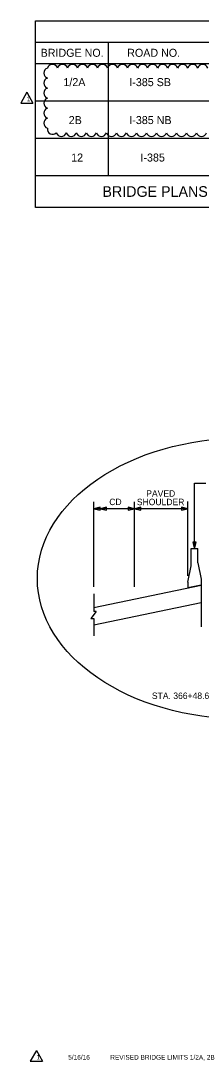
# Model space of a CAD drawing. Extents: x 4832 to 5477, y 4935 to 5220.
# Drawn here: x 5015.4 to 5049.2, y 5022.4 to 5217.4 of the extents above; entities that cross this region are included whole.
import ezdxf

# ---------------------------------------------------------------- set-up
doc = ezdxf.new("R2010")
doc.units = 0
for name, color, linetype in [('Level 2', 7, 'Continuous'), ('Level 3', 7, 'Continuous'), ('Level 42', 7, 'Continuous'), ('RD_SHT_TX', 7, 'Continuous'), ('RD_SHT_Typical', 7, 'Continuous'), ('RD_TX_TitleSht', 7, 'Continuous'), ('RD_TX_TypSect', 7, 'Continuous'), ('RD_XS_PaveShd', 7, 'Continuous'), ('TERMINATOR', 7, 'Continuous')]:
    doc.layers.add(name, color=color, linetype=linetype)

# ---------------------------------------------------------------- blocks, each defined once
blk = doc.blocks.new('AH')
at = {"layer": 'TERMINATOR'}
blk.add_lwpolyline([(-6, 1.5), (0, 0), (-6, -1.5)], close=True, dxfattribs=at)

msp = doc.modelspace()

# ---------------------------------------------------------------- linework, layer by layer
at = {"layer": 'Level 2'}
for p, q in [((5047.34, 5115.27), (5047.35, 5118.48)), ((5047.35, 5118.48), (5048.59, 5118.48)), ((5048.6, 5115.8), (5048.59, 5118.48)), ((5046.72, 5112.21), (5047.34, 5115.27)), ((5048.6, 5115.8), (5049.22, 5112.73)), ((5046.72, 5112.21), (5046.72, 5111.11)), ((5049.22, 5111.63), (5046.72, 5111.11)), ((5049.22, 5112.73), (5049.22, 5111.63))]:
    msp.add_line(p, q, dxfattribs=at)
at = {"layer": 'Level 3'}
for p, q in [((5018.15, 5188.42), (5018.15, 5217.42)), ((5018.15, 5217.42), (5115.75, 5217.42)), ((5018.15, 5213.42), (5115.75, 5213.42)), ((5018.15, 5209.42), (5115.75, 5209.42)), ((5018.15, 5202.42), (5115.75, 5202.42)), ((5018.15, 5195.42), (5115.75, 5195.42)), ((5018.15, 5188.42), (5115.75, 5188.42)), ((5031.75, 5188.42), (5115.75, 5188.42))]:
    msp.add_line(p, q, dxfattribs=at)
at = {"layer": 'Level 42'}
msp.add_lwpolyline([(5018.15, 5188.42), (5115.75, 5188.42), (5115.75, 5182.42), (5018.15, 5182.42)], close=True, dxfattribs=at)
at = {"layer": 'RD_SHT_TX'}
for p, q in [((5016.53, 5204.04), (5015.39, 5202.01)), ((5016.53, 5204.04), (5017.67, 5202.01)), ((5015.39, 5202.01), (5017.67, 5202.01)), ((5018.31, 5024.44), (5017.17, 5022.41)), ((5018.31, 5024.44), (5019.45, 5022.41)), ((5017.17, 5022.41), (5019.45, 5022.41))]:
    msp.add_line(p, q, dxfattribs=at)
for centre, radius, start, end in [((5020.68, 5207.62), 0.985, 107.5, 252.5), ((5021.32, 5208.27), 0.985, 17.5, 162.5), ((5023.2, 5208.27), 0.985, 17.5, 162.5), ((5025.08, 5208.27), 0.985, 17.5, 162.5), ((5026.96, 5208.27), 0.985, 17.5, 162.5), ((5028.84, 5208.27), 0.985, 17.5, 162.5), ((5030.71, 5208.27), 0.985, 17.5, 162.5), ((5032.59, 5208.27), 0.985, 17.5, 162.5), ((5034.47, 5208.27), 0.985, 17.5, 162.5), ((5036.35, 5208.27), 0.985, 17.5, 162.5), ((5038.23, 5208.27), 0.985, 17.5, 162.5), ((5040.1, 5208.27), 0.985, 17.5, 162.5), ((5041.98, 5208.27), 0.985, 17.5, 162.5), ((5043.86, 5208.27), 0.985, 17.5, 162.5), ((5045.74, 5208.27), 0.985, 17.5, 162.5), ((5047.62, 5208.27), 0.985, 17.5, 162.5), ((5049.5, 5208.27), 0.985, 17.5, 162.5), ((5020.68, 5205.74), 0.985, 107.5, 252.5), ((5020.68, 5203.87), 0.985, 107.5, 252.5), ((5020.68, 5201.99), 0.985, 107.5, 252.5), ((5020.68, 5200.11), 0.985, 107.5, 252.5), ((5020.68, 5198.23), 0.985, 107.5, 252.5), ((5021.35, 5197.12), 0.984, 169.7993, 314.7993), ((5022.99, 5196.72), 0.985, 197.5, 342.5), ((5024.86, 5196.72), 0.985, 197.5, 342.5), ((5026.74, 5196.72), 0.985, 197.5, 342.5), ((5028.62, 5196.72), 0.985, 197.5, 342.5), ((5030.5, 5196.72), 0.985, 197.5, 342.5), ((5032.38, 5196.72), 0.985, 197.5, 342.5), ((5034.25, 5196.72), 0.985, 197.5, 342.5), ((5036.13, 5196.72), 0.985, 197.5, 342.5), ((5038.01, 5196.72), 0.985, 197.5, 342.5), ((5039.89, 5196.72), 0.985, 197.5, 342.5), ((5041.77, 5196.72), 0.985, 197.5, 342.5), ((5043.65, 5196.72), 0.985, 197.5, 342.5), ((5045.52, 5196.72), 0.985, 197.5, 342.5), ((5047.4, 5196.72), 0.985, 197.5, 342.5), ((5049.28, 5196.72), 0.985, 197.5, 342.5)]:
    msp.add_arc(centre, radius, start, end, dxfattribs=at)
at = {"layer": 'RD_SHT_Typical'}
for p, q in [((5029.08, 5110.03), (5029.08, 5106.71)), ((5029.52, 5106.71), (5028.51, 5105.37)), ((5028.51, 5105.37), (5029.08, 5105.37)), ((5029.52, 5106.71), (5029.08, 5106.71)), ((5029.08, 5105.37), (5029.08, 5102.12))]:
    msp.add_line(p, q, dxfattribs=at)
at = {"layer": 'RD_TX_TitleSht'}
msp.add_line((5031.75, 5213.42), (5031.75, 5188.42), dxfattribs=at)
at = {"layer": 'RD_TX_TypSect'}
for p, q in [((5047.97, 5118.48), (5047.97, 5130.76)), ((5047.97, 5130.76), (5050.08, 5130.76)), ((5029.08, 5111.31), (5029.08, 5127.23)), ((5036.72, 5111.31), (5036.72, 5127.23)), ((5046.72, 5113.37), (5046.72, 5127.34)), ((5036.72, 5125.97), (5029.08, 5125.97)), ((5046.72, 5125.97), (5036.72, 5125.97))]:
    msp.add_line(p, q, dxfattribs=at)
msp.add_ellipse((5057.12, 5112.88), major_axis=(38.62, 0), ratio=0.681891, dxfattribs=at)
at = {"layer": 'RD_XS_PaveShd'}
for p, q in [((5029.08, 5107.44), (5049.22, 5111.63)), ((5049.21, 5111.63), (5049.22, 5103.83)), ((5029.08, 5104.22), (5049.22, 5108.41))]:
    msp.add_line(p, q, dxfattribs=at)

# ---------------------------------------------------------------- block references
at = {"layer": 'TERMINATOR', "xscale": 0.2000217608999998, "yscale": -0.20002176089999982}
for p, rotation in [((5029.08, 5125.97), -179.998582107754), ((5030.28, 5125.97), -179.998582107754), ((5036.72, 5125.97), 0.0014178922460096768), ((5036.72, 5125.97), -179.998582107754), ((5046.72, 5125.97), 0.0014178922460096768), ((5047.97, 5118.48), -89.998582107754)]:
    msp.add_blockref('AH', p, dxfattribs=dict(at, rotation=rotation))

# ---------------------------------------------------------------- texts
at = {"layer": 'Level 3'}
for s, height, p in [('BRIDGE NO.', 1.5, (5019.11, 5210.67)), ('ROAD NO.', 1.5, (5035.34, 5210.67)), ('1/2A', 1.5, (5023.38, 5205.17)), ('I-385 SB', 1.5, (5035.74, 5205.17)), ('2B', 1.5, (5024.38, 5198.06)), ('I-385 NB', 1.5, (5035.74, 5198.06)), ('12', 1.5, (5024.84, 5191.04)), ('I-385', 1.5, (5037.83, 5191.04)), ('BRIDGE PLANS BOUND UNDER SEPARATE COVER', 2, (5030.69, 5184.42))]:
    msp.add_text(s, height=height, rotation=360, dxfattribs=at).set_placement(p)
at = {"layer": 'RD_SHT_TX'}
for s, p in [('1', (5016.53, 5202.34)), ('1', (5018.31, 5022.74)), ('5/16/16', (5024.28, 5022.7)), ('REVISED BRIDGE LIMITS 1/2A, 2B', (5032.17, 5022.7))]:
    msp.add_text(s, height=0.88, dxfattribs=at).set_placement(p)
at = {"layer": 'RD_TX_TypSect'}
for s, p in [('PAVED', (5038.91, 5128.22)), ('CD', (5031.98, 5126.64)), ('SHOULDER', (5037.15, 5126.63)), ('STA. 366+48.64 TO STA. 384+00', (5039.97, 5090.31))]:
    msp.add_text(s, height=1.2, dxfattribs=at).set_placement(p)

doc.saveas('drawing.dxf')
